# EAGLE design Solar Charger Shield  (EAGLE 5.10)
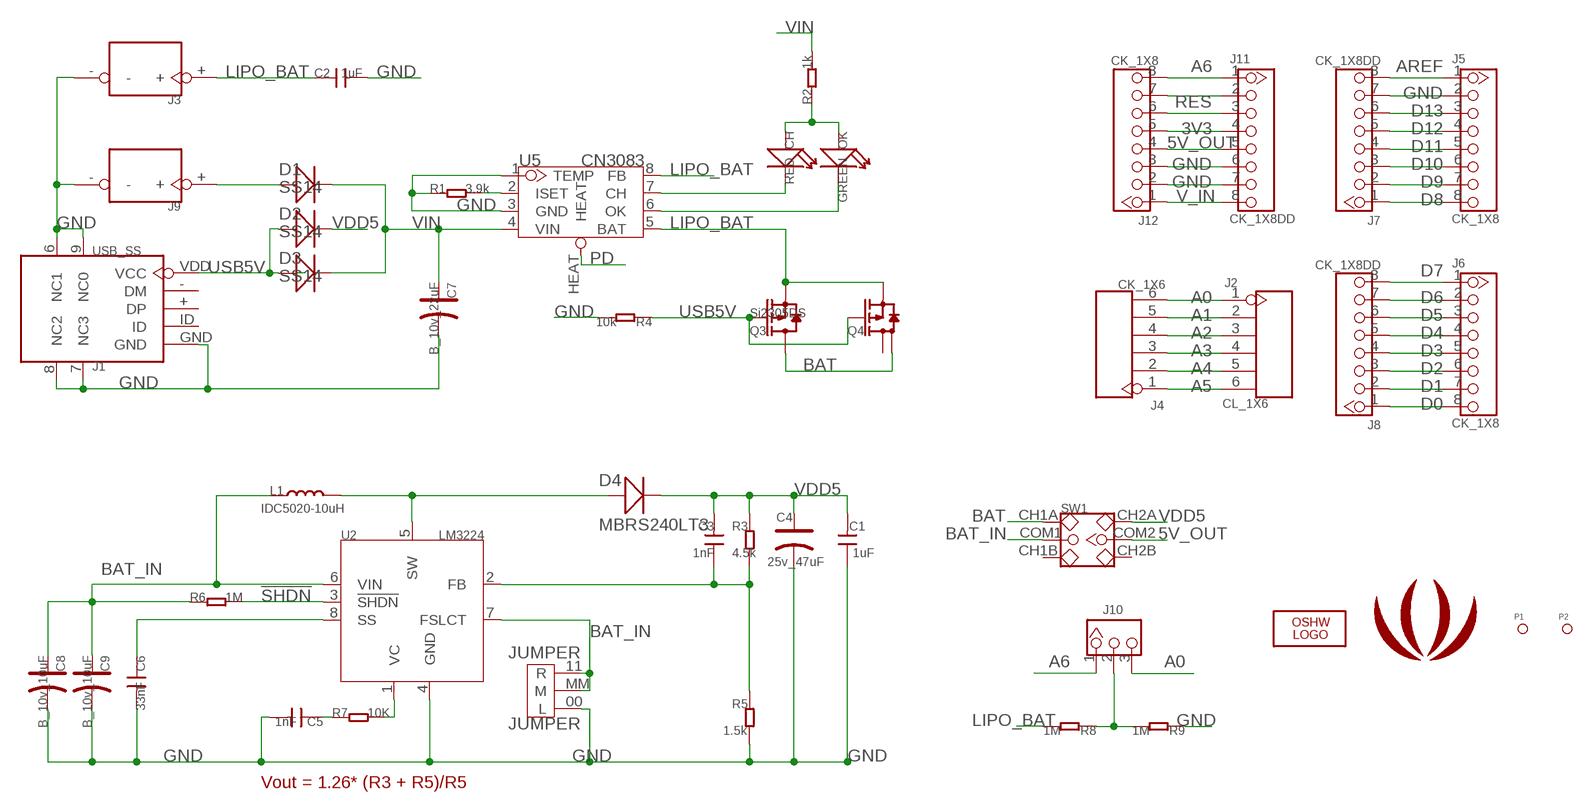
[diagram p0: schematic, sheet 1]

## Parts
C1  1uF  C-0805  [0805]
C2  1uF  C-0805  [0805]
C3  1nF  C-0603  [0603]
C4  25v_47uF  CAP_AVX_C  [AVX-C]
C5  1nF  C-0603  [0603]
C6  33nF  C-0603  [0603]
C7  B_10v_22uF  CAP_AVX_B  [AVX-B]
C8  B_10v_10uF  CAP_AVX_B  [AVX-B]
C9  B_10v_10uF  CAP_AVX_B  [AVX-B]
CH  RED  LED-0603  [D0603]
D1  SS14  D-2010  [D2010]
D2  SS14  D-2010  [D2010]
D3  SS14  D-2010  [D2010]
D4  MBRS240LT3  D-240LT3  [MBRS240LT3]
J1  USB_SS  [USB_B_S]
J2  CL_1X6  CK_1X6  [CK_1X6]
J3  JACK-2P-2.54  [PW-2P-2.54-6.35X7.62-DIP]
J4  CK_1X6  [CK_1X6]
J5  CK_1X8  CK_1X8DD  [CK_1X8]
J6  CK_1X8  CK_1X8DD  [CK_1X8]
J7  CK_1X8DD  [CK_1X8]
J8  CK_1X8DD  [CK_1X8]
J9  JACK-2P-2.54  [PW-2P-2.54-6.35X7.62-DIP]
J10  HEADER-3P-2.54  [3P-2.54-LEADED]
J11  CK_1X8DD  [CK_1X8]
J12  CK_1X8  CK_1X8DD  [CK_1X8]
JUMPER  JUMPER  [JUMPER]
L1  IDC5020-10uH  L-5020  [5020]
LOGO1  LOGO-OSHW-FILLX0200-NT  [OSHW_FILLX200_NOTEXT]
OK  GREEN  LED-0603  [D0603]
P1  PAD-MARK  [ROUND-MARK-0.635]
P2  PAD-MARK  [ROUND-MARK-0.635]
Q3  Si2305DS  010-P-MOSFETSOT23  [SOT23]
Q4  NDT2955_SOT223  [SOT223]
R1  3.9k  R-0603  [0603]
R2  1k  R-0603  [0603]
R3  4.5k  R-0603  [0603]
R4  10k  R-0603  [0603]
R5  1.5k  R-0603  [0603]
R6  1M  R-0603  [0603]
R7  10K  R-0603  [0603]
R8  1M  R-0603  [0603]
R9  1M  R-0603  [0603]
SW1  SWITCH-2CH-6P'90'  [6P-LEADED-2CH-2.54-90-3.6X9.0]
U2  LM3224  [MSOP08]
U5  CN3083  [SOP8]
U$1  LOGO-SEEEDSTUDIO-SILK  [LOGO_SILK]

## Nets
3V3: J11.4 J12.5
5V_OUT: J11.5 J12.4 SW1.COM2
!SHDN: R6.2 U2.3(!SHDN)
A0: J2.1 J4.6 J10.3
A1: J2.2 J4.5
A2: J2.3 J4.4
A3: J2.4 J4.3
A4: J2.5 J4.2
A5: J2.6 J4.1
A6: J10.1 J11.1 J12.8
AREF: J5.1 J7.8
BAT: Q3.3(D) Q4.4(D) SW1.CH1A
BAT_IN: C8.+ C9.+ JUMPER.11(R) JUMPER.MM(M) L1.1 R6.1 SW1.COM1 U2.6(VIN) U2.7(FSLCT)
D0: J6.8 J8.1
D1: J6.7 J8.2
D2: J6.6 J8.3
D3: J6.5 J8.4
D4: J6.4 J8.5
D5: J6.3 J8.6
D6: J6.2 J8.7
D7: J6.1 J8.8
D8: J5.8 J7.1
D9: J5.7 J7.2
D10: J5.6 J7.3
D11: J5.5 J7.4
D12: J5.4 J7.5
D13: J5.3 J7.6
FB: C3.1 R3.2 R5.1 U2.2(FB)
GND: C1.1 C2.2 C4.- C5.2 C6.2 C7.- C8.- C9.- J1.6(NC1) J1.7(NC3) J1.8(NC2) J1.9(NC0) J1.GND J3.- J5.2 J7.7 J9.- J11.6 J11.7 J12.2 J12.3 JUMPER.00(L) R1.1 R4.2 R5.2 R9.1 U2.4(GND) U5.1(TEMP) U5.3(GND)
LIPO_BAT: C2.1 J3.+ Q3.2(S) Q4.3(S) R8.2 U5.5(BAT) U5.8(FB)
N$1: J10.2 R8.1 R9.2
N$2: D1.+ J9.+
N$6: J11.2 J12.7
N$13: R1.2 U5.2(ISET)
N$14: CH.- U5.7(CH)
N$15: OK.- U5.6(OK)
N$16: CH.+ OK.+ R2.1
N$18: C6.1 U2.8(SS)
N$19: D4.+ L1.2 U2.5(SW)
N$20: R7.2 U2.1(VC)
N$21: C5.1 R7.1
PD: U5.HEAT
RES: J11.3 J12.6
USB5V: D2.+ D3.+ J1.VDD(VCC) Q3.1(G) Q4.1(G) R4.1
V_IN: J11.8 J12.1
VDD5: C1.2 C3.2 C4.+ D2.- D4.- R3.1 SW1.CH2A
VIN: C7.+ D1.- D3.- R2.2 U5.4(VIN)
Unconnected: J1.+(DP) J1.-(DM) J1.ID Q4.2(D) SW1.CH1B SW1.CH2B

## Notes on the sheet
- Vout = 1.26* (R3 + R5)/R5

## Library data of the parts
C1-C3 C5 C6 = Discrete:C*: Ceramic Capacitors
C4 C7-C9 = Discrete:CAP*: Electrolytic Capacitors,Tantalum Capacitors and Super Capacitors
CH OK = Discrete:LED*
D1-D4 = Discrete:D*
J1 = CONNECTER:USB
J2 J4 = CONNECTER:CK_1X6
J3 J9 = Connector:JACK-2P
J5-J8 J11 J12 = CONNECTER:CK_1X8
J10 = Connector:HEADER-3P
JUMPER = CPT_SMD:JUMPER
L1 = Discreter:L*
LOGO1 = Logo:LOGO-OSHW-FILL
P1 P2 = Discreter:PAD-MARK
Q3 = Discrete:010-P-MOSFET*: Si2305DS Si2323CDS
Q4 = Discrete:NDT2955
R1-R9 = Discrete:R*
SW1 = Discreter:SWITCH-2CH-6P
U2 = ICs:LM3224
U5 = ICs_v54:CN3083
U$1 = Logo:LOGO-SEEEDSTUDIO

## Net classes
0 default: width 0.203 mm, drill 0.305 mm, clearance 0.127 mm

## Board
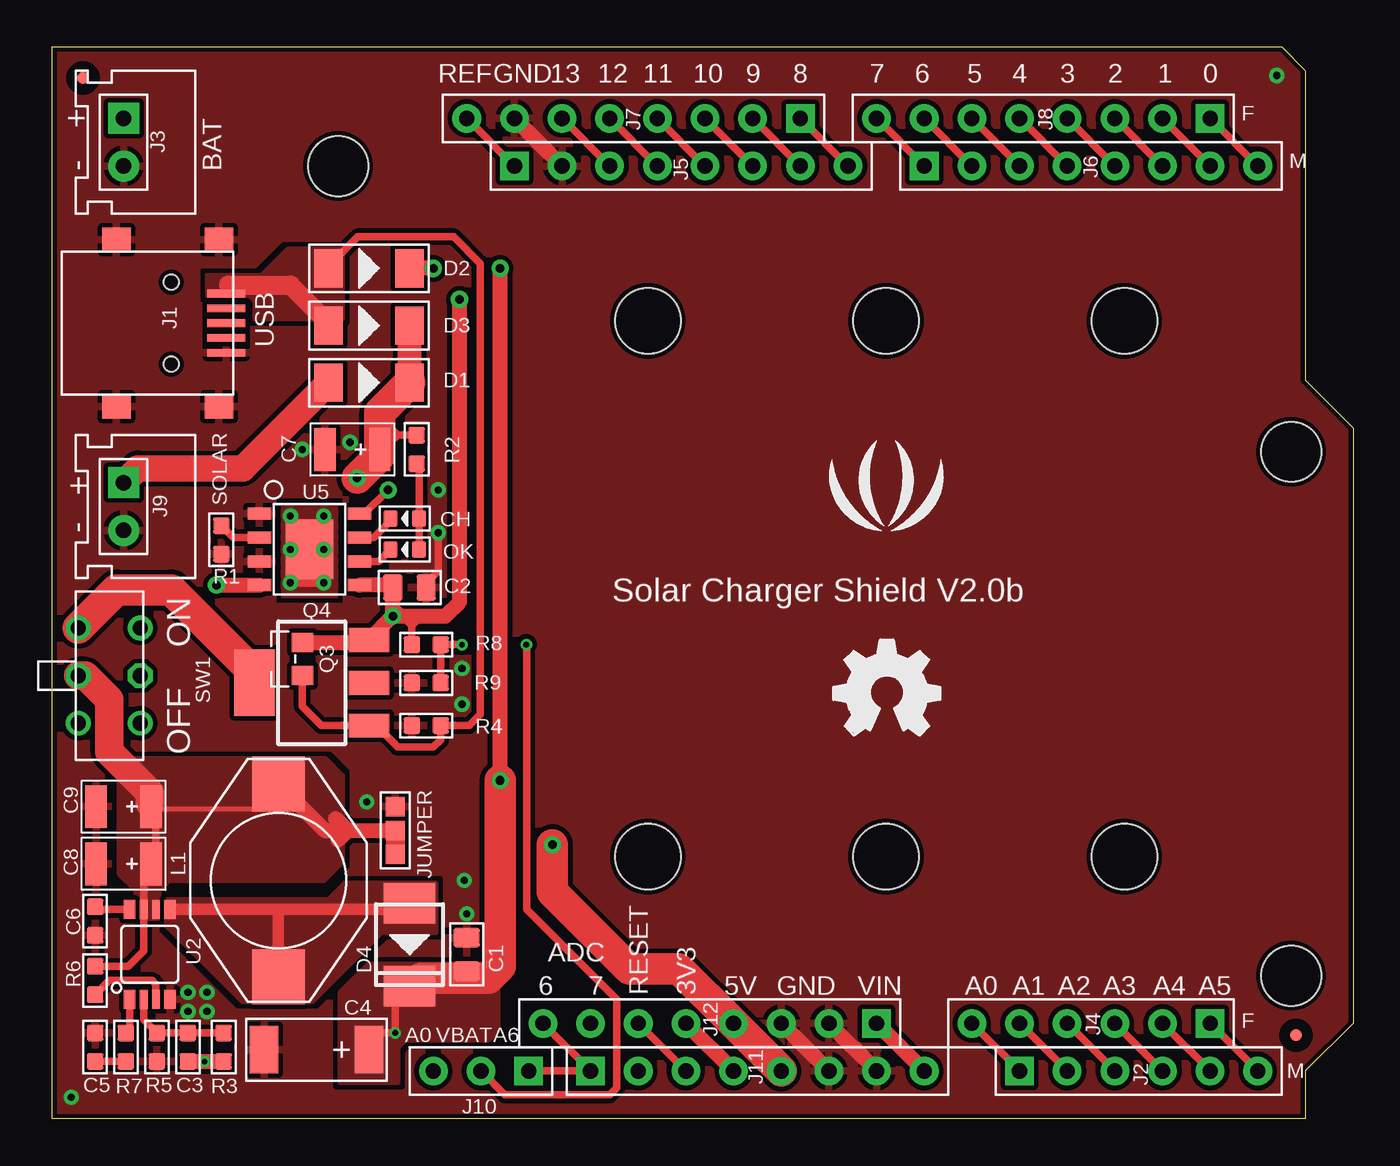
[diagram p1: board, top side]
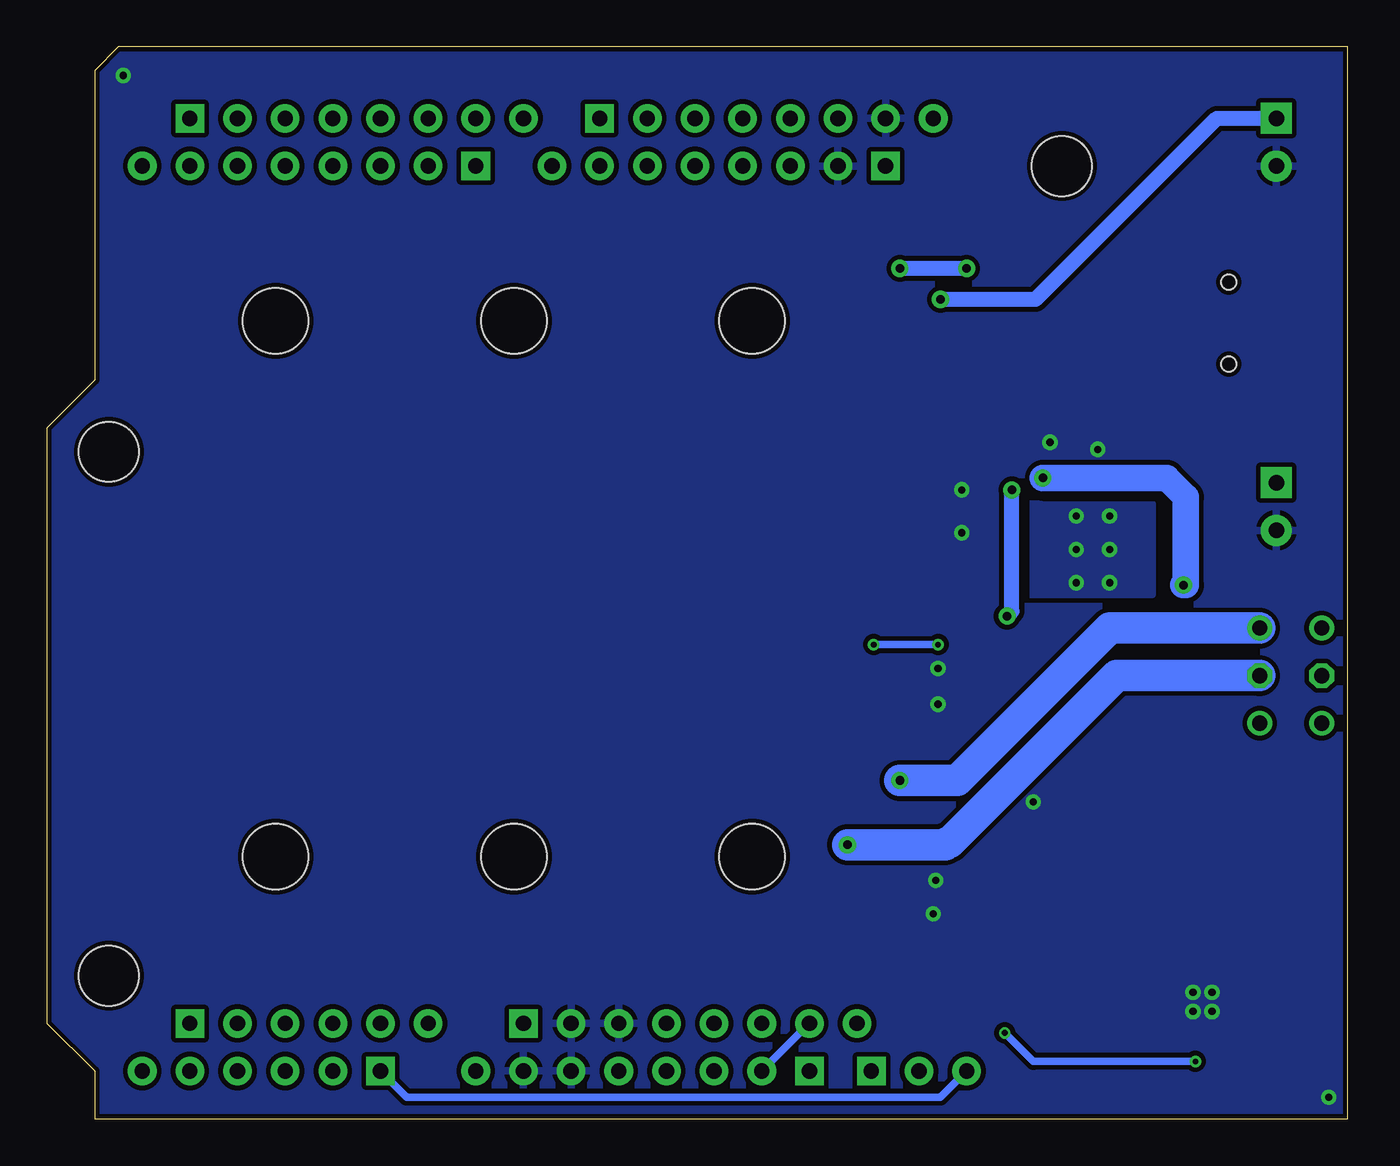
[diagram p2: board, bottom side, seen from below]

Size 69.34 x 57.15 mm. Coordinates in mm from the lower left corner, seen from the top.
Outline: 0,0 0,57.15 65.53,57.15 66.8,55.88 66.8,39.37 69.34,36.83 69.34,5.08 66.8,2.54 66.8,0 0,0
Copper layers (1*16): Top 0.035mm / dielectric 1.5mm / Bottom 0.035mm
Design rules "SeeedStudio_rule_no_angle_090911 *": minimum track width 6mil, minimum drill 12mil, track to track 6mil, track to pad 6mil, pad to pad 6mil, via to via 6mil, smd to smd 0mil, copper to edge 10mil, drill to drill 10mil, minimum pad ring 10mil, minimum via ring 6mil, stop-mask expansion 2mil, vias tented up to drill 100mil, thermal gap 10mil
Holes 3.2 mm at 15.24,50.8 66.04,7.62 66.04,35.56
Holes 3.5 mm at 31.75,42.55 44.45,42.55 57.15,42.55 31.75,13.97 44.45,13.97 57.15,13.97

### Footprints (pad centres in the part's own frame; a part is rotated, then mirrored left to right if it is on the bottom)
0805 = smd 1.016 x 1.397: 1 -0.889,0; 2 0.889,0
0603 = smd 0.889 x 0.889: 1 -0.762,0; 2 0.762,0
AVX-C = smd 1.524 x 2.54: + -2.794,0; - 2.794,0
AVX-B = smd 1.143 x 2.286: + -1.46,0; - 1.46,0
D0603 = smd 0.762 x 0.889: + -0.762,0; - 0.762,0
D2010 = smd 1.524 x 2.032: + -2.159,0; - 2.159,0
MBRS240LT3 = smd 2.159 x 2.743: + 2.21,0; - -2.21,0
USB_B_S = smd 1.524 x 1.27: 6 0.762,-4.445; 7 6.223,-4.445; 8 6.223,4.445; 9 0.762,4.445 | smd 2.032 x 0.406: + 0.381,0; - 0.381,-0.787; GND 0.381,1.575; ID 0.381,0.787; VDD 0.381,-1.575 | hole 0.813: 3.302,2.184; 3.302,-2.184
CK_1X6 = drill 0.813 pad 1.524 square: 1 0,6.35 | drill 0.813 pad 1.524 round: 2 0,3.81; 3 0,1.27; 4 0,-1.27; 5 0,-3.81; 6 0,-6.35
PW-2P-2.54-6.35X7.62-DIP = drill 0.813 pad 1.651 square: + 1.27,0 | drill 0.813 pad 1.651 round: - -1.27,0
CK_1X8 = drill 0.813 pad 1.524 square: 1 0,8.89 | drill 0.813 pad 1.524 round: 2 0,6.35; 3 0,3.81; 4 0,1.27; 5 0,-1.27; 6 0,-3.81; 7 0,-6.35; 8 0,-8.89
3P-2.54-LEADED = drill 0.813 pad 1.524 square: 1 0,2.54 | drill 0.813 pad 1.524 round: 2 0,0; 3 0,-2.54
JUMPER = smd 1.016 x 1.016: 00 -1.27,0; 11 1.27,0; MM 0,0
5020 = smd 2.92 x 2.79: 1 -5.145,0; 2 5.145,0
ROUND-MARK-0.635 = smd 0.635 x 0.635: P$1 0,0
SOT23 = smd 1.016 x 1.143: 1 -0.889,-1.016; 2 0.889,-1.016; 3 0,1.016
SOT223 = smd 1.27 x 2.159: 1 -2.286,-3.048; 2 0,-3.048; 3 2.286,-3.048 | smd 3.556 x 2.159: 4 0,3.048
6P-LEADED-2CH-2.54-90-3.6X9.0 = drill 0.813 pad 1.27 round: CH1A -2.54,-1.65; CH1B 2.54,-1.65; CH2A -2.54,1.65; CH2B 2.54,1.65 | drill 0.813 pad 1.27 octagon: COM1 0,-1.65; COM2 0,1.65
MSOP08 = smd 1.016 x 0.61: 1 -2.4,1.077; 4 -2.4,-1.077; 5 2.4,-1.077; 8 2.4,1.077 | smd 1.016 x 0.406: 2 -2.4,0.325; 3 -2.4,-0.325; 6 2.4,-0.325; 7 2.4,0.325
SOP8 = smd 0.635 x 1.27: 1 -1.905,-2.667; 2 -0.635,-2.667; 3 0.635,-2.667; 4 1.905,-2.667; 5 1.905,2.667; 6 0.635,2.667; 7 -0.635,2.667; 8 -1.905,2.667 | smd 3.175 x 2.54: HEAT 0,0

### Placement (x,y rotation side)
C1  22.1,8.76 270 top
C2  19.05,28.32 0 top
C3  7.24,3.81 270 top
C4  14.1,3.68 180 top
C5  2.29,3.81 90 top
C6  2.29,10.54 270 top
C7  16,35.69 180 top
C8  3.81,13.59 180 top
C9  3.81,16.64 180 top
CH  18.8,32 180 top
D1  16.89,39.24 0 top
D2  16.89,45.34 0 top
D3  16.89,42.29 0 top
D4  19.05,9.27 90 top
J1  9.65,42.42 180 top
J2  57.91,2.54 90 top
J3  3.81,52.07 90 top
J4  55.37,5.08 270 top
J5  33.53,50.8 90 top
J6  55.37,50.8 90 top
J7  30.99,53.34 270 top
J8  52.83,53.34 270 top
J9  3.81,32.64 90 top
J10  22.86,2.54 270 top
J11  37.59,2.54 90 top
J12  35.05,5.08 270 top
JUMPER  18.29,15.37 270 top
L1  12.06,12.7 270 top
LOGO1  41.66,20.45 0 top
OK  18.8,30.35 180 top
P1  1.65,55.5 0 top
P2  66.29,4.45 0 top
Q3  12.32,24.51 90 top
Q4  13.84,23.24 90 top
R1  9.02,30.86 90 top
R2  19.43,35.69 90 top
R3  9.14,3.81 90 top
R4  19.94,20.95 180 top
R5  5.59,3.81 270 top
R6  2.29,7.37 270 top
R7  3.94,3.81 90 top
R8  19.94,25.27 180 top
R9  19.94,23.24 0 top
SW1  3.05,23.62 270 top
U2  5.21,8.76 90 top
U5  13.72,30.35 270 top
U$1  44.45,33.02 0 top

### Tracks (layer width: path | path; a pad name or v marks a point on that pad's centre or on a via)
3V3
  Top 0.813: J12.5 J11.4
5V_OUT  (via drill 0.46 pad 0.91)
  Top 1.676: J11.5 J12.4 33.4,8 30.76,8 26.67,12.09 v26.67,14.61
  Bottom 1.676: v26.67,14.61 21.46,14.61 21.34,14.73 21.21,14.73 12.32,23.62 SW1.COM2
!SHDN
  Top 0.406: U2.3 5.53,7.17 5.33,7.37 3.05,7.37 R6.2
A0
  Top 0.406: J2.1 J4.6
  Bottom 0.406: J2.1 50.16,1.14 21.72,1.14 20.95,1.91 J10.3
A1
  Top 0.406: J4.5 J2.2
A2
  Top 0.406: J4.4 J2.3
A3
  Top 0.406: J4.3 J2.4
A4
  Top 0.406: J4.2 J2.5
A5
  Top 0.406: J4.1 J2.6
A6
  Top 0.406: J12.8 J11.1 J10.1
AREF
  Top 0.406: J7.8 J5.1
BAT
  Top 0.305: Q4.4 11.68,23.24
  Top 0.406: Q3.3 11.3,23.75 10.99,23.43 10.41,22.86
  Top 1.27: 10.41,22.86 Q4.4
  Top 1.676: SW1.CH1A 3.43,28.19 6.35,28.19 10.67,23.88 10.67,23.75 10.99,23.43
BAT_IN
  Top 0.254: 5.52,16.51 10.73,16.51 L1.1
  Top 0.406: R6.1 4.06,8.13 4.88,8.95 U2.7 4.88,13.2 C8.+ 5.59,13.59 5.52,13.65 5.52,16.51
  Top 0.813: 15.75,15.37 14.54,15.37 L1.1 | 15.75,15.37 15.11,16 | 15.75,15.37 JUMPER.MM | 15.75,15.37 15.24,14.86
  Top 1.016: JUMPER.MM JUMPER.11
  Top 1.524: SW1.COM1 1.78,23.62 3.05,22.35 3.05,19.56 5.21,17.4 5.21,16.83
  pour Top (isolate 0.254, no thermals): 5.71,10.67 5.71,12.19 6.22,12.7 14.48,12.7 15.49,13.72 15.49,18.29 14.61,19.18 6.99,19.18 4.01,19.18 3.56,18.72 3.56,13.08 4.45,12.19 4.45,10.67
D0
  Top 0.406: J8.1 J6.8
D1
  Top 0.406: J8.2 J6.7
D2
  Top 0.406: J8.3 J6.6
D3
  Top 0.406: J8.4 J6.5
D4
  Top 0.406: J8.5 J6.4
D5
  Top 0.406: J8.6 J6.3
D6
  Top 0.406: J8.7 J6.2
D7
  Top 0.406: J8.8 J6.1
D8
  Top 0.406: J7.1 J5.8
D9
  Top 0.406: J7.2 J5.7
D10
  Top 0.406: J7.3 J5.6
D11
  Top 0.406: J7.4 J5.5
D12
  Top 0.406: J7.5 J5.4
D13
  Top 0.406: J7.6 J5.3
FB
  Top 0.406: U2.2 4.88,5.28 R5.1 C3.1 R3.2
GND  (via drill 0.38 pad 0.81)
  Top 0.406: C2.2 19.94,28.57 20.57,29.21 v20.57,31.24
  Top 0.813: J7.7 J5.2 | J12.3 J11.6 | J12.2 J11.7
  other vias: 7.24,6.73 8.26,5.71 7.24,5.71 1.02,1.14 8.26,6.73 20.57,33.53 13.34,35.69 65.28,55.63 15.88,36.07 21.84,24 21.84,22.1 22.1,10.92 21.97,12.7 16.76,16.89
  pour Top (isolate 0.254, rank 3): -0.13,57.28 70.48,57.15 69.85,0 -0.25,0
  pour Bottom (isolate 0.254, rank 3): -0.25,57.4 70.61,57.28 69.85,0 -0.25,0
LIPO_BAT  (via drill 0.46 pad 0.91)
  Top 0.406: U5.8 16.64,32.26 v17.91,33.53 | R8.2 19.18,26.16 19.18,26.29 | 19.43,26.8 19.18,26.54 19.18,26.29 | 19.18,26.29 18.92,26.54 | 19.18,26.29 19.56,26.67
  Top 0.813: Q3.2 16.76,25.4 Q4.3 v18.16,26.8 | v18.16,26.8 18.16,27.18 | 18.16,27.18 C2.1 18.03,28.45 U5.5 | v18.16,26.8 18.54,26.8 | v21.72,43.69 21.72,27.56 20.95,26.8 19.43,26.8 18.54,26.8 | 18.16,27.18 18.54,26.8
  Bottom 0.813: v21.72,43.69 16.64,43.69 6.99,53.34 J3.+ | v17.91,33.53 17.91,27.05 v18.16,26.8
N$1  (via drill 0.3)
  Top 0.406: R9.2 R8.1 v21.84,25.27 | J10.2 24.13,1.27 29.72,1.27 30.1,1.65 30.1,6.35 25.3,11.15 25.3,25.25 v25.27,25.27
  Bottom 0.406: v25.27,25.27 v21.84,25.27
N$2
  Top 1.422: D1.+ 10.16,34.67 4.57,34.67 J9.+
N$6
  Bottom 0.406: J11.2 J12.7
N$13
  Top 0.406: U5.2 9.65,30.99 R1.2
N$14
  Top 0.406: U5.7 17.14,30.99 18.03,31.88 CH.-
N$15
  Top 0.406: U5.6 17.4,29.72 OK.-
N$16
  Top 0.406: OK.+ CH.+ 19.56,34.8 R2.1
N$18
  Top 0.406: U2.8 2.43,11.16 C6.1
N$19
  Top 0.61: 12.06,11.16 U2.5 | 12.06,11.16 18.73,11.16 D4.+ | L1.2 12.06,11.16
  pour Top (isolate 0.254, rank 2, no thermals): 5.97,11.68 14.73,11.68 15.62,12.57 20.45,12.57 20.45,9.91 17.53,9.91 13.84,6.22 10.16,6.22 5.97,10.41
N$20
  Top 0.406: U2.1 4.13,4.76 R7.2
N$21
  Top 0.406: C5.1 R7.1
PD  (via drill 0.38 pad 0.81)
  Top 0.406: v14.48,28.57 v12.7,28.57
  other vias: 12.7,32.13 14.48,32.13 12.7,30.35 14.48,30.35
  pour Top (isolate 0.508, no thermals): 11.94,32.64 15.62,32.64 15.62,27.94 11.94,27.94
  pour Bottom (isolate 0.508, no thermals): 10.41,32.77 16.89,32.77 16.89,27.94 10.41,27.94
RES
  Top 0.406: J12.6 J11.3
USB5V
  Top 0.254: J1.VDD 9.27,44.32 9.4,44.45
  Top 0.406: Q3.1 13.34,21.97 14.35,20.95 Q4.1 17.27,20.95 18.41,19.81 20.32,19.81 20.7,20.19 R4.1 22.23,20.95 22.83,21.56 22.83,45.6 21.39,47.03 16.3,47.03 14.73,45.47 D2.+
  Top 0.813: 14.86,42.16 14.86,41.91 14.73,42.04 D3.+ 14.86,42.16 | 14.17,42.98 14.22,42.93 14.86,42.29 14.86,42.16
  Top 1.016: 9.4,44.45 12.7,44.45 14.22,42.93
  pour Top (isolate 0.381, no thermals): 8.26,42.67 15.49,42.67 15.49,46.35 12.57,46.35 11.18,44.96 8.26,44.96
V_IN
  Top 0.813: J11.8 J12.1
VDD5  (via drill 0.3, 0.46 pad 0.91)
  Top 0.406: C4.+ 16.89,4.06 17.4,4.57 v18.29,4.57 18.29,6.3 D4.-
  Top 0.813: 19.05,45.54 19,45.49 19.05,45.44 D2.- v20.32,45.34 | R3.1 v8.13,3.05 C3.2 | v23.88,18.03 v23.88,45.34
  Top 1.676: 19.68,7.49 23.24,7.49 23.88,8.13 v23.88,18.03
  Bottom 0.406: v8.13,3.05 16.76,3.05 v18.29,4.57
  Bottom 0.813: v23.88,45.34 v20.32,45.34
  Bottom 1.676: v23.88,18.03 20.83,18.03 12.7,26.16 SW1.CH2A
  pour Top (isolate 0.254, no thermals): 15.37,1.91 15.37,6.73 16.89,8.26 22.86,8.26 23.75,7.37 23.75,4.7 23.24,4.19 18.8,4.19 18.41,3.81 18.41,1.91
VIN  (via drill 0.46 pad 0.91)
  Top 0.406: 17.46,36.45 18.41,36.45 | 18.41,36.45 18.03,36.83 | 18.41,36.45 R2.2 | 18.41,36.45 18.03,36.07
  Top 0.813: v8.76,28.45 U5.4
  Top 1.27: D1.- D3.-
  Top 1.422: 17.46,35.94 17.4,35.88
  Top 1.676: D1.- 17.46,37.66 17.46,36.45 17.46,35.94 C7.+ 17.46,35.37 v16.26,34.16
  Bottom 1.422: v8.76,28.45 8.64,28.45 8.64,33.15 9.65,34.16 v16.26,34.16

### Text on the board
tPlace: REF | GND | 13 | 12 | 11 | 10 | 9 | 8 | 7 | 6 | 5 | 4 | 3 | 2 | 1 | 0 | + | F | - | BAT | M | USB | SOLAR | + | - | Solar Charger Shield V2.0b | ON | OFF | ADC | 6 | 7 | RESET | 3V3 | 5V | GND | VIN | A0 | A1 | A2 | A3 | A4 | A5 | F | A0 | VBAT | A6 | M
tNames: J7 | J8 | J5 | J6 | C9 | J4 | J2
